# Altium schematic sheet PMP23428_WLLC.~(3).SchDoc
size 431 x 279 mm; Date: Not shown in title block; ApprovedBy: Not shown in title block; CheckedBy: Not shown in title block; Author: Not shown in title block; CompanyName: Not shown in title block; Engineer: Not shown in title block; Organization: Not shown in title block; Address1: Not shown in title block; Address2: Not shown in title block; Address3: Not shown in title block; Address4: Not shown in title block; DocumentNumber: 1; Revision: Use project parameter SCH_Rev; SheetNumber: 3; SheetTotal: 4; PageSetup: Record=PageOptions¦CenterHorizontal=True¦CenterVertical=True¦PrintScale=1.00¦XCorrection=1.00¦YCorrection=1.00¦PrintKind=0¦BorderSize=5000000¦LeftOffset=0¦BottomOffset=0¦Orientation=2¦PaperLength=1000¦PaperWidth=1000¦Scale=100¦PaperSource=15¦PrintQuality=600¦MediaType=1¦DitherType=10¦PaperKind=Letter¦PrintScaleMode=1
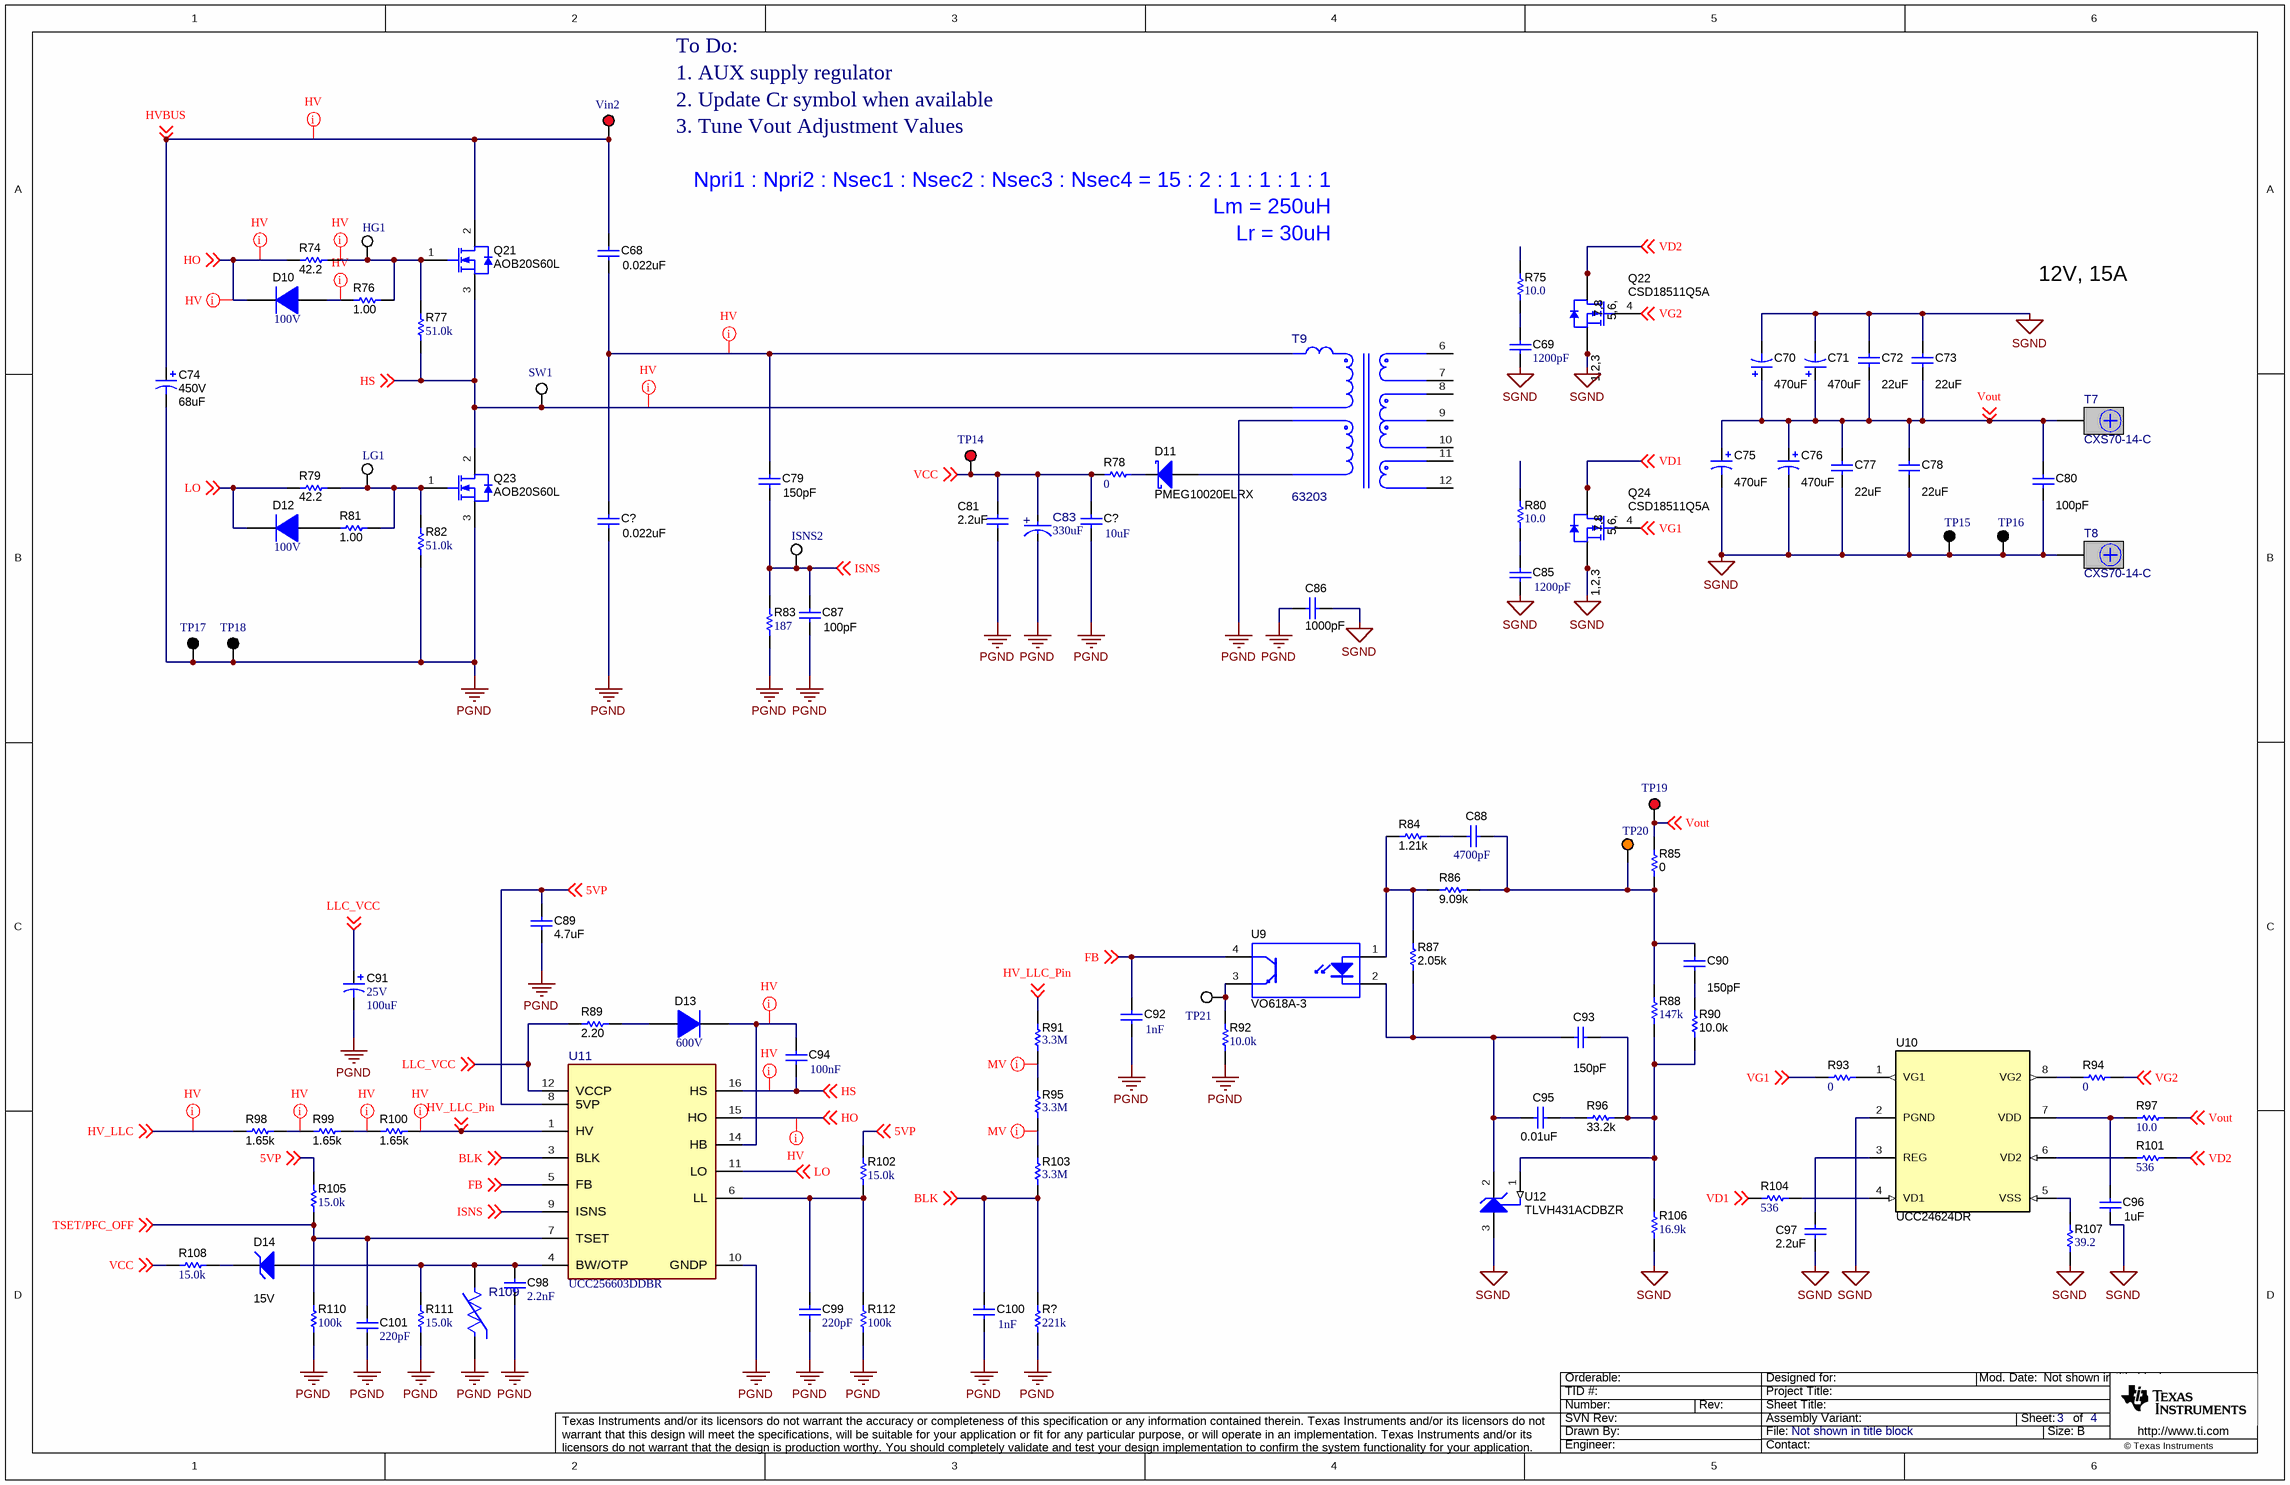
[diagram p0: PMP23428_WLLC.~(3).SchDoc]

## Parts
(Parts that share a designator on the sheet are numbered #1, #2 ... from top to bottom, then left to right.)
C68  ValueDisplayed: 0.022uF  [B32652_1800x700x1250]  (hidden comment: B32652A7153J000)
C69  ValueDisplayed: 1200pF  [0805L]  (hidden comment: GRM2165C2A122JA01D)
C70  ValueDisplayed: 470uF  [HW_1000x1600]  (hidden comment: UHW1V471MPD)
C71  ValueDisplayed: 470uF  [HW_1000x1600]  (hidden comment: UHW1V471MPD)
C72  ValueDisplayed: 22uF  [1206_190L]  (hidden comment: C3216X5R1E226M160AB)
C73  ValueDisplayed: 22uF  [1206_190L]  (hidden comment: C3216X5R1E226M160AB)
C74  VDC_V: 450V  ValueDisplayed: 68uF  [KXG_1800x3150]  (hidden comment: EKXG451ELL680MMN3S)
C75  ValueDisplayed: 470uF  [HW_1000x1600]  (hidden comment: UHW1V471MPD)
C76  ValueDisplayed: 470uF  [HW_1000x1600]  (hidden comment: UHW1V471MPD)
C77  ValueDisplayed: 22uF  [1206_190L]  (hidden comment: C3216X5R1E226M160AB)
C78  ValueDisplayed: 22uF  [1206_190L]  (hidden comment: C3216X5R1E226M160AB)
C79  ValueDisplayed: 150pF  [1206L]  (hidden comment: GRM31A5C2J151JW01D)
C80  ValueDisplayed: 100pF  [0603L]  (hidden comment: 06035A101FAT2A)
C81  ValueDisplayed: 2.2uF  [0805L]  (hidden comment: C2012X7R1V225K085AC)
C83  ValueDisplayed: 330uF  [FP-35ZL330MEFC10X16_RADIAL-MFG]  (hidden comment: 35ZL330MEFC10X16)
C85  ValueDisplayed: 1200pF  [0805L]  (hidden comment: GRM2165C2A122JA01D)
C86  ValueDisplayed: 1000pF  [CD45_700x600x1100]  (hidden comment: CD45-E2GA102M-NKA)
C87  ValueDisplayed: 100pF  [1206L]  (hidden comment: 12061A101JAT2A)
C88  ValueDisplayed: 4700pF  [0603L]  (hidden comment: C0603C472J1GAC7867)
C89  ValueDisplayed: 4.7uF  [1206L]  (hidden comment: C3216X7R1E475K085AB)
C90  ValueDisplayed: 150pF  [0402L]  (hidden comment: 885012005062)
C91  VDC_V: 25V  ValueDisplayed: 100uF  [SM_RADIAL_E]  (hidden comment: EEE-FK1E101P)
C92  Cap_F: 1nF  [1206L]  (hidden comment: 12061A102JAT2A)
C93  ValueDisplayed: 150pF  [0402L]  (hidden comment: 885012005062)
C94  Cap_F: 100nF  [1206_180L]  (hidden comment: GRM31C5C1E104JA01L)
C95  ValueDisplayed: 0.01uF  [0603L]  (hidden comment: 06031C103JAT2A)
C96  ValueDisplayed: 1uF  [0603L]  (hidden comment: GRM188R71C105KE15D)
C97  ValueDisplayed: 2.2uF  [0805L]  (hidden comment: C2012X7R1V225K085AC)
C98  Cap_F: 2.2nF  [0603]  (hidden comment: C0603X222K5RACTU)
C99  Cap_F: 220pF  [0603]  (hidden comment: C0603X221K5RACTU)
C100  Cap_F: 1nF  [0402L]  (hidden comment: 04025C102JAT2A)
C101  Cap_F: 220pF  [0603]  (hidden comment: C0603X221K5RACTU)
C?#1  ValueDisplayed: 0.022uF  [B32652_1800x700x1250]  (hidden comment: B32652A7153J000)
C?#2  ValueDisplayed: 10uF  [1210_270]  (hidden comment: GRM32ER6YA106KA12L)
D10  Vr_V: 100V  [SOD-123]  (hidden comment: 1N4148W-7-F)
D11  PMEG10020ELRX  [SOD-123W]
D12  Vr_V: 100V  [SOD-123]  (hidden comment: 1N4148W-7-F)
D13  Vr_V: 600V  [SMAF]  (hidden comment: ES1JAF)
D14  value 15V  [SOD-123]  (hidden comment: DDZ15-7)
HG1  5012  [Keystone5012]  (value not drawn)
ISNS2  5012  [Keystone5012]  (value not drawn)
LG1  5012  [Keystone5012]  (value not drawn)
Q21  AOB20S60L  [DDPAK]
Q22  CSD18511Q5A  [DQJ0008A]
Q23  AOB20S60L  [DDPAK]
Q24  CSD18511Q5A  [DQJ0008A]
R74  ValueDisplayed: 42.2  [0603]  (hidden comment: RC0603FR-0742R2L)
R75  ValueDisplayed: 10.0  [1206L]  (hidden comment: RC1206FR-0710RL)
R76  ValueDisplayed: 1.00  [0603L]  (hidden comment: RC0603FR-071RL)
R77  ValueDisplayed: 51.0k  [0603L]  (hidden comment: RC0603FR-0751KL)
R78  ValueDisplayed: 0  [1206L]  (hidden comment: ERJ-8GEY0R00V)
R79  ValueDisplayed: 42.2  [0603L]  (hidden comment: RC0603FR-0742R2L)
R80  ValueDisplayed: 10.0  [1206L]  (hidden comment: RC1206FR-0710RL)
R81  ValueDisplayed: 1.00  [0603L]  (hidden comment: RC0603FR-071RL)
R82  ValueDisplayed: 51.0k  [0603L]  (hidden comment: RC0603FR-0751KL)
R83  ValueDisplayed: 187  [1206]  (hidden comment: RC1206FR-07187RL)
R84  ValueDisplayed: 1.21k  [0603L]  (hidden comment: RC0603FR-071K21L)
R85  ValueDisplayed: 0  [0402L]  (hidden comment: RC0402JR-070RL)
R86  ValueDisplayed: 9.09k  [0603L]  (hidden comment: RC0603FR-079K09L)
R87  ValueDisplayed: 2.05k  [0603L]  (hidden comment: RC0603FR-072K05L)
R88  ValueDisplayed: 147k  [0603L]  (hidden comment: RC0603FR-07147KL)
R89  ValueDisplayed: 2.20  [0603L]  (hidden comment: ERJ-3RQF2R2V)
R90  ValueDisplayed: 10.0k  [0603L]  (hidden comment: ERJ-3EKF1002V)
R91  Res_ohm: 3.3M  [FP-KTR18EZPF3304_1206-MFG]  (hidden comment: KTR18EZPF3304)
R92  ValueDisplayed: 10.0k  [0402L]  (hidden comment: ERJ-2RKF1002X)
R93  ValueDisplayed: 0  [0603L]  (hidden comment: RC0603JR-070RL)
R94  ValueDisplayed: 0  [0603L]  (hidden comment: RC0603JR-070RL)
R95  Res_ohm: 3.3M  [FP-KTR18EZPF3304_1206-MFG]  (hidden comment: KTR18EZPF3304)
R96  ValueDisplayed: 33.2k  [0603L]  (hidden comment: RC0603FR-0733K2L)
R97  ValueDisplayed: 10.0  [0603L]  (hidden comment: RC0603FR-0710RL)
R98  ValueDisplayed: 1.65k  [1206L]  (hidden comment: CRCW12061K65FKEA)
R99  ValueDisplayed: 1.65k  [1206L]  (hidden comment: CRCW12061K65FKEA)
R100  ValueDisplayed: 1.65k  [1206L]  (hidden comment: CRCW12061K65FKEA)
R101  ValueDisplayed: 536  [0603L]  (hidden comment: RT0603BRD07536RL)
R102  ValueDisplayed: 15.0k  [0603]  (hidden comment: RT0603BRD0715KL)
R103  Res_ohm: 3.3M  [FP-KTR18EZPF3304_1206-MFG]  (hidden comment: KTR18EZPF3304)
R104  ValueDisplayed: 536  [0603L]  (hidden comment: RT0603BRD07536RL)
R105  ValueDisplayed: 15.0k  [0603]  (hidden comment: RT0603BRD0715KL)
R106  ValueDisplayed: 16.9k  [0603L]  (hidden comment: RC0603FR-0716K9L)
R107  ValueDisplayed: 39.2  [0603L]  (hidden comment: RC0603FR-0739R2L)
R108  ValueDisplayed: 15.0k  [0603]  (hidden comment: RG1608P-153-B-T5)
R109  B57371V2474J060  [FP-B57371V2474J060_0603-MFG]  (value not drawn)
R110  ValueDisplayed: 100k  [0603]  (hidden comment: RT0603BRD07100KL)
R111  ValueDisplayed: 15.0k  [0603]  (hidden comment: RG1608P-153-B-T5)
R112  ValueDisplayed: 100k  [0603]  (hidden comment: RT0603BRD07100KL)
R?  ValueDisplayed: 221k  [0603]  (hidden comment: RC0603FR-07221KL)
SW1  5012  [Keystone5012]  (value not drawn)
T7  CXS70-14-C  [Panduit_CXS70-14-C]
T8  CXS70-14-C  [Panduit_CXS70-14-C]
T9  63203  [FP-63203_W80MM0_H64MM0-MFG]
TP14  5010  [Keystone5010]  (value not drawn)
TP15  5011  [Keystone5011]  (value not drawn)
TP16  5011  [Keystone5011]  (value not drawn)
TP17  5011  [Keystone5011]  (value not drawn)
TP18  5011  [Keystone5011]  (value not drawn)
TP19  5010  [Keystone5010]  (value not drawn)
TP20  5013  [Keystone5013]  (value not drawn)
TP21  5012  [Keystone5012]  (value not drawn)
U9  VO618A-3  [DIP-4]
U10  UCC24624DR  [D0008A_N]
U11  UCC256603DDBR  [DDB0014A-MFG]
U12  TLVH431ACDBZR  [DBZ0003A_N]
Vin2  5010  [Keystone5010]  (value not drawn)

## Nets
PGND: C74.2(-) C81.2 C83.1(CATHODE) C86.2 C87.2 C89.2 C91.2(-) C92.2 C98.2 C99.2 C100.2 C101.2 C?#1.2 C?#2.2 Q23.3(S) R82.1 R83.1 R92.1 R109.1 R110.1 R111.1 R112.1 R?.1 TP17.1 TP18.1 U11.10(GNDP)
SGND: C69.2 C70.2(-) C71.2(-) C72.1 C73.1 C75.2(-) C76.2(-) C77.2 C78.2 C80.2 C85.2 C86.1 C96.2 C97.2 Q22.1(S) Q22.2(S) Q22.3(S) Q24.1(S) Q24.2(S) Q24.3(S) R106.1 R107.2 T8.1 TP15.1 TP16.1 U10.2(PGND) U12.3(ANODE)
5VP: C89.1 R102.2 R105.2 U11.8(5VP) ; off-sheet 5VP
BLK: C100.1 R103.1 R?.2 U11.3(BLK) ; off-sheet BLK
FB: C92.1 U9.4(C) U11.5(FB) ; off-sheet FB
HO: D10.1(K) R74.1 U11.15(HO) ; off-sheet HO
HS: C94.2 Q21.3(S) Q23.2(D) R77.1 SW1.1 U11.16(HS) ; off-sheet HS
HV_LLC: R98.1 ; off-sheet HV_LLC
HV_LLC_Pin: R91.2 R100.2 U11.1(HV) ; off-sheet HV_LLC_Pin
HVBUS: C68.1 C74.1(+) Q21.2(D) Vin2.1 ; off-sheet HVBUS
ISNS: C79.2 C87.1 ISNS2.1 R83.2 U11.9(ISNS) ; off-sheet ISNS
LLC_VCC: C91.1(+) R89.1 U11.12(VCCP) ; off-sheet LLC_VCC
LO: D12.1(K) R79.1 U11.11(LO) ; off-sheet LO
TSET/PFC_OFF: C101.1 R105.1 R110.2 U11.7(TSET) ; off-sheet TSET/PFC_OFF
VCC: C81.1 C83.2(ANODE) C?#2.1 R78.1 R108.2 TP14.1 ; off-sheet VCC
VD1: Q24.5(D) Q24.6(D) Q24.7(D) Q24.8(D) Q24.9(D) R104.2 ; off-sheet VD1
VD2: Q22.5(D) Q22.6(D) Q22.7(D) Q22.8(D) Q22.9(D) R101.1 ; off-sheet VD2
VG1: Q24.4(G) R93.1 ; off-sheet VG1
VG2: Q22.4(G) R94.2 ; off-sheet VG2
Vout: C70.1(+) C71.1(+) C72.2 C73.2 C75.1(+) C76.1(+) C77.1 C78.1 C80.1 R85.2 R97.2 T7.1 TP19.1 ; off-sheet Vout
NetC68_2: C68.2 C79.1 C?#1.1
NetC69_1: C69.1 R75.1
NetC85_1: C85.1 R80.1
NetC88_1: C88.1 C90.1 R85.1 R86.2 R88.2 TP20.1
NetC88_2: C88.2 R84.2
NetC90_2: C90.2 R90.2
NetC93_1: C93.1 R88.1 R90.1 R96.1 R106.2 U12.1(REF)
NetC93_2: C93.2 C95.2 R87.1 U9.2(K) U12.2(CATHODE)
NetC94_1: C94.1 D13.1(K) U11.14(HB)
NetC95_1: C95.1 R96.2
NetC96_1: C96.1 R97.1 U10.7(VDD)
NetC97_1: C97.1 U10.3(REG)
NetC98_1: C98.1 D14.2(A) R109.2 R111.2 U11.4(BW/OTP)
NetC99_1: C99.1 R102.1 R112.2 U11.6(LL)
NetD10_2: D10.2(A) R76.1
NetD11_1: D11.1(K) R78.2
NetD12_2: D12.2(A) R81.1
NetD13_2: D13.2(A) R89.2
NetD14_1: D14.1(K) R108.1
NetHG1_1: HG1.1 Q21.1(G) R74.2 R76.2 R77.2
NetLG1_1: LG1.1 Q23.1(G) R79.2 R81.2 R82.2
NetR84_1: R84.1 R86.1 R87.2 U9.1(A)
NetR91_1: R91.1 R95.2
NetR92_2: R92.2 TP21.1 U9.3(E)
NetR93_2: R93.2 U10.1(VG1)
NetR94_1: R94.1 U10.8(VG2)
NetR95_1: R95.1 R103.2
NetR98_2: R98.2 R99.1
NetR99_2: R99.2 R100.1
NetR101_2: R101.2 U10.6(VD2)
NetR104_1: R104.1 U10.4(VD1)
NetR107_1: R107.1 U10.5(VSS)

Not connected (* = marked no-connect by the designer): D11 2(A); R75 2; R80 2; T9 6 7 8 9 10 11 12

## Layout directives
net class HV: HO, HS, HV_LLC, HV_LLC_Pin, HVBUS, NetC68_2, NetC94_1, NetD10_2, NetHG1_1, NetR98_2, NetR99_2
net class MV: NetR91_1, NetR95_1

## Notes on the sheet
- To Do:
- 1. AUX supply regulator
- 2. Update Cr symbol when available
- 3. Tune Vout Adjustment Values
- Lm = 250uH
- Lr = 30uH
- Npri1 : Npri2 : Nsec1 : Nsec2 : Nsec3 : Nsec4 = 15 : 2 : 1 : 1 : 1 : 1
- 12V, 15A

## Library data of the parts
C68 C?#1 = CMP-0012346-3: Manufacturer: TDK; TaMin_C: -55°C; Polarized: N; SizeAreaWB_mm2: 180; Value1: Unknown; Value: 0.015uF; TaMax_C: 100°C; Tolerance_%: 5%; SizeZ_mm: 12.5; SizeX_mm: 18; SizeY_mm: 7; Cap_Case: 18x7x12.5; Value2: 1250V; SizeArea_mm2: 126; CompType: Capacitor; AEC Qualified: Y; Cap_F: 15nF; VDC_V: 1.25kV; AEC Grade: 3; AEC Category: Q200
C69 C85 = CMP-0008098-2: CAP, CERM, 1200 pF, 100 V, +/- 5%, C0G/NP0, 0805; Manufacturer: MuRata; TaMin_C: -55°C; Polarized: N; SizeAreaWB_mm2: 6.75; Value1: Unknown; U/M: EA; Value: 1200pF; TaMax_C: 125°C; SizeZ_mm: 1.45; SizeX_mm: 2; SizeY_mm: 1.25; Cap_Case: 0805; Value2: 100V; SizeArea_mm2: 2.5; Cap_F: 1.2nF; AEC Category: Q200
C70 C71 C75 C76 = CMP-0010541-2: CAP, AL, 470 uF, 35 V, +/- 20%, 0.03 ohm, TH; Manufacturer: Nichicon; TaMin_C: -40°C; ESR_ohm: 0.03; Polarized: Y; SizeAreaWB_mm2: 144; U/M: EA; Value: 470uF; TaMax_C: 105°C; SizeZ_mm: 17.5; SizeX_mm: 10; Cap_Case: 10x16mm; Value2: 35V; SizeArea_mm2: 100; CompType: Capacitor; AEC Qualified: N; Cap_F: 470µF; IRMS_A: 2A; AEC Category: Q200
C72 C73 C77 C78 = CMP-0008654-2: CAP, CERM, 22 uF, 25 V, +/- 20%, X5R, 1206_190; Manufacturer: TDK; TaMin_C: -55°C; Polarized: N; SizeAreaWB_mm2: 10.92; Value1: Unknown; U/M: EA; Value: 22uF; TaMax_C: 85°C; SizeZ_mm: 1.9; SizeX_mm: 3.2; SizeY_mm: 1.6; Cap_Case: 1206; Value2: 25V; SizeArea_mm2: 5.12; CompType: Capacitor; Cap_F: 22µF; AEC Category: Q200
C74 = CMP-0010043-2: CAP, AL, 68 uF, 450 V, +/- 20%, TH; Manufacturer: Chemi-Con; TaMin_C: -25°C; Polarized: Y; SizeAreaWB_mm2: 400; Value1: Unknown; U/M: EA; Value: 68uF; TaMax_C: 105°C; SizeZ_mm: 33; SizeX_mm: 18; Cap_Case: 18x31.5mm; SizeArea_mm2: 324; CompType: Capacitor; Cap_F: 68µF; IRMS_A: 6.3dA; AEC Category: Q200
C79 = CMP-0008885-2: CAP, CERM, 150 pF, 630 V, +/- 5%, C0G/NP0, 1206; Manufacturer: MuRata; TaMin_C: -55°C; Polarized: N; SizeAreaWB_mm2: 10.92; Value1: Unknown; U/M: EA; Value: 150pF; TaMax_C: 125°C; SizeZ_mm: 1.35; SizeX_mm: 3.2; SizeY_mm: 1.6; Cap_Case: 1206; Value2: 630V; SizeArea_mm2: 5.12; CompType: Capacitor; AEC Category: Q200
C80 = CMP-0006762-4: CAP, CERM, 100 pF, 50 V, +/- 1%, C0G/NP0, 0603; Manufacturer: AVX; TaMin_C: -55°C; Polarized: N; SizeAreaWB_mm2: 4.68; Value1: Unknown; U/M: EA; TaMax_C: 125°C; SizeZ_mm: 1; SizeX_mm: 1.6; SizeY_mm: 0.8; Cap_Case: 0603; Value2: 50V; SizeArea_mm2: 1.28; CompType: Capacitor; Value: 100pF; AEC Category: Q200
C81 C97 = CMP-0007883-2: CAP, CERM, 2.2 uF, 35 V, +/- 10%, X7R, 0805; Manufacturer: TDK; TaMin_C: -55°C; Polarized: N; SizeAreaWB_mm2: 6.75; Value1: Unknown; U/M: EA; Value: 2.2uF; TaMax_C: 125°C; SizeZ_mm: 1.45; SizeX_mm: 2; SizeY_mm: 1.25; Cap_Case: 0805; Value2: 35V; SizeArea_mm2: 2.5; CompType: Capacitor; Cap_F: 2.2µF; AEC Category: Q200
C83 = CMP-0098283-1: Cap Aluminum Lytic 330uF 35V 20% (10 X 16mm) Radial 5mm 1430mA 4000h 105C Bulk; Manufacturer: Rubycon; AEC Qualified: No; Cap_F: 330µF; IRMS_A: 1.43A; SizeZ_mm: 17.5mm; Dissipation Factor: 12%; Leakage Current: 115.5uA; Life: 4000Hours; Value: 330µF
C86 = CMP-0009595-2: CAP, CERM, 1000 pF,  V, +/- 20%, E, D7xT6mm; Manufacturer: TDK; TaMin_C: -25°C; Polarized: N; SizeAreaWB_mm2: 101.2; Value1: Unknown; U/M: EA; Value: 1000pF; TaMax_C: 125°C; SizeZ_mm: 11; SizeX_mm: 10.65; SizeY_mm: 6; Cap_Case: 7x6x11mm; SizeArea_mm2: 63.9; Cap_F: 1nF; AEC Category: Q200
C87 = CMP-0008462-2: CAP, CERM, 100 pF, 100 V, +/- 5%, C0G/NP0, 1206; Manufacturer: AVX; TaMin_C: -55°C; ESR_ohm: 7.01d; Polarized: N; SizeAreaWB_mm2: 10.92; Value1: 0.701 ohm; U/M: EA; Value: 100pF; TaMax_C: 125°C; SizeZ_mm: 1.35; SizeX_mm: 3.2; SizeY_mm: 1.6; Cap_Case: 1206; Value2: 100V; SizeArea_mm2: 5.12; CompType: Capacitor; AEC Category: Q200
C88 = CMP-0006941-4: CAP, CERM, 4700 pF, 100 V, +/- 5%, C0G/NP0, 0603; Manufacturer: Kemet; TaMin_C: -55°C; Polarized: N; SizeAreaWB_mm2: 4.68; Value1: Unknown; U/M: EA; Value: 4700pF; TaMax_C: 125°C; SizeZ_mm: 1; SizeX_mm: 1.6; SizeY_mm: 0.8; Cap_Case: 0603; Value2: 100V; SizeArea_mm2: 1.28; Cap_F: 4.7nF; AEC Category: Q200
C89 = CMP-0008693-2: CAP, CERM, 4.7 uF, 25 V, +/- 10%, X7R, 1206; Manufacturer: TDK; TaMin_C: -55°C; Polarized: N; SizeAreaWB_mm2: 10.92; Value1: Unknown; U/M: EA; Value: 4.7uF; TaMax_C: 125°C; SizeZ_mm: 1.35; SizeX_mm: 3.2; SizeY_mm: 1.6; Cap_Case: 1206; Value2: 25V; SizeArea_mm2: 5.12; CompType: Capacitor; Cap_F: 4.7µF; AEC Category: Q200
C90 C93 = CMP-0064913-2: CAP, CERM, 150 pF, 50 V,+/- 5%, C0G/NP0, 0402; Manufacturer: Wurth Elektronik; TaMin_C: -55°C; Polarized: N; SizeAreaWB_mm2: 3; Value1: Unknown; U/M: EA; Value: 150pF; TaMax_C: 125°C; SizeZ_mm: 0.6; SizeX_mm: 1; SizeY_mm: 0.5; Cap_Case: 0402; Value2: 50V; CompType: Capacitor; AEC Category: Q200
C91 = CMP-0010710-1: CAP, AL, 100 uF, 25 V, +/- 20%, 0.26 ohm, AEC-Q200 Grade 2, SMD; Manufacturer: Panasonic; TaMin_C: -55°C; ESR_ohm: 2.6d; Polarized: Y; SizeAreaWB_mm2: 118.45; U/M: EA; Value: 100uF; TaMax_C: 105°C; SizeZ_mm: 6.2; SizeX_mm: 9.5; SizeY_mm: 8.3; Cap_Case: E; SizeArea_mm2: 78.85; CompType: Capacitor; Cap_F: 100µF; IRMS_A: 3dA; AEC Grade: 2; AEC Category: Q200
C92 = CMP-0008465-2: CAP, CERM, 1000 pF, 100 V, +/- 5%, C0G/NP0, 1206; Manufacturer: AVX; TaMin_C: -55°C; ESR_ohm: 2.38d; Polarized: N; SizeAreaWB_mm2: 10.92; Value1: 0.238 ohm; U/M: EA; Value: 1000pF; TaMax_C: 125°C; SizeZ_mm: 1.35; SizeX_mm: 3.2; SizeY_mm: 1.6; Cap_Case: 1206; Value2: 100V; SizeArea_mm2: 5.12; AEC Category: Q200
C94 = CMP-0064950-2: CAP, CERM, 0.1 uF, 25 V,+/- 5%, C0G/NP0, 1206; Manufacturer: MuRata; TaMin_C: -55°C; Polarized: N; SizeAreaWB_mm2: 10.92; Value1: Unknown; U/M: EA; Value: 0.1uF; TaMax_C: 125°C; SizeZ_mm: 1.8; SizeX_mm: 3.2; SizeY_mm: 1.6; Cap_Case: 1206; Value2: 25V; SizeArea_mm2: 5.12; AEC Category: Q200
C95 = CMP-0006726-4: CAP, CERM, 0.01 uF, 100 V, +/- 5%, X7R, 0603; Manufacturer: AVX; TaMin_C: -55°C; ESR_ohm: 0.098; Polarized: N; SizeAreaWB_mm2: 4.68; Value1: 0.098 ohm; U/M: EA; Value: 0.01uF; TaMax_C: 125°C; SizeZ_mm: 1; SizeX_mm: 1.6; SizeY_mm: 0.8; Cap_Case: 0603; Value2: 100V; SizeArea_mm2: 1.28; Cap_F: 10nF; AEC Category: Q200
C96 = CMP-0007380-4: CAP, CERM, 1 uF, 16 V, +/- 10%, X7R, 0603; Manufacturer: MuRata; TaMin_C: -55°C; Polarized: N; SizeAreaWB_mm2: 4.68; Value1: Unknown; U/M: EA; Value: 1uF; TaMax_C: 125°C; SizeZ_mm: 1; SizeX_mm: 1.6; SizeY_mm: 0.8; Cap_Case: 0603; Value2: 16V; SizeArea_mm2: 1.28; CompType: Capacitor; Cap_F: 1µF; AEC Category: Q200
C98 = CMP-0006983-4: CAP, CERM, 2200 pF, 50 V, +/- 10%, X7R, 0603; Manufacturer: Kemet; TaMin_C: -55°C; Polarized: N; SizeAreaWB_mm2: 4.68; Value1: Unknown; U/M: EA; Value: 2200pF; TaMax_C: 125°C; SizeZ_mm: 1; SizeX_mm: 1.6; SizeY_mm: 0.8; Value2: 50V; SizeArea_mm2: 1.28; AEC Category: Q200
C99 C101 = CMP-0006982-4: CAP, CERM, 220 pF, 50 V, +/- 10%, X7R, 0603; Manufacturer: Kemet; TaMin_C: -55°C; Polarized: N; SizeAreaWB_mm2: 4.68; Value1: Unknown; U/M: EA; Value: 220pF; TaMax_C: 125°C; SizeZ_mm: 1; SizeX_mm: 1.6; SizeY_mm: 0.8; Value2: 50V; SizeArea_mm2: 1.28; AEC Category: Q200
C100 = CMP-0861060-1: CAP, CERM, 1000 pF, 50 V,+/- 5%, X7R, 0402; Manufacturer: AVX; Value2: 50V; SizeY_mm: 0.5; AEC Category: Q200; Polarized: N; Green_Lifecycle: Active; SizeAreaWB_mm2: 3; ValueDisplayed: 1000pF; Cap_Case: 0402; Value: 1000pF; TaMin_C: -55°C; U/M: EA; Green_REACh: Passed; SizeZ_mm: 0.6; SizeX_mm: 1; TaMax_C: 125°C
C?#2 = CMP-0009215-2: CAP, CERM, 10 uF, 35 V, +/- 10%, X5R, 1210; Manufacturer: MuRata; TaMin_C: -55°C; Polarized: N; SizeAreaWB_mm2: 14.7; Value1: Unknown; U/M: EA; Value: 10uF; TaMax_C: 85°C; SizeZ_mm: 2.7; SizeX_mm: 3.2; SizeY_mm: 2.5; Cap_Case: 1210; Value2: 35V; SizeArea_mm2: 8; Cap_F: 10µF; AEC Category: Q200
D10 D12 = CMP-0029001-2: Diode, Ultrafast, 100 V, 0.15 A, SOD-123; Manufacturer: Diodes Inc.; Io_A: 150mA; Green_Lifecycle: Active; SizeAreaWB_mm2: 13.095; Green_REACh: Passed; Value1: 0.15A; TJmax_C: 150°C; Value: 100V; SizeZ_mm: 1.35; SizeX_mm: 3.85; SizeY_mm: 1.7; Vf_V: 1.25V; SizeArea_mm2: 6.545; AEC Category: Q101
D11 = CMP-0028977-2: Diode, Schottky, 100 V, 2 A, AEC-Q101, SOD-123W; Manufacturer: Nexperia; Io_A: 2A; SizeAreaWB_mm2: 12.15; Vr_V: 100V; TJmax_C: 175°C; Value: 100V; SizeZ_mm: 1; SizeX_mm: 3.5; SizeY_mm: 1.7; Vf_V: 830mV; Value2: 0.83V; SizeArea_mm2: 5.95; AEC Qualified: Y; AEC Category: Q101
D13 = CMP-0029162-2: Diode, Ultrafast, 600 V, 1 A, AEC-Q101, SMAF; Manufacturer: Fairchild Semiconductor; Io_A: 1A; Green_Lifecycle: Not Set; SizeAreaWB_mm2: 19.95; Green_REACh: Incomplete; TJmax_C: 150°C; Value: 600V; SizeZ_mm: 1; SizeX_mm: 4.7; SizeY_mm: 2.5; Vf_V: 1.7V; SizeArea_mm2: 11.75; AEC Qualified: Y; AEC Category: Q101
D14 = CMP-0085135-1: Diode, Zener, 15 V, 500 mW, SOD-123; Manufacturer: Diodes Inc.; SizeAreaWB_mm2: 13.095; SizeArea_mm2: 6.545; SizeY_mm: 1.7; AEC Qualified: N; SizeZ_mm: 1.35; Value1: 0.5W; SizeX_mm: 3.85; Power_W: 500mW; RJA_CperW: 425; AEC Category: Q101
HG1 ISNS2 LG1 SW1 TP21 = CMP-0055149-2: Test Point, Multipurpose, White, TH; Manufacturer: Keystone Electronics; CNHeader: FALSE; Green_Lifecycle: Active; Green_REACh: Passed; ContactFinish: Silver; CT: TRUE
Q21 Q23 = CMP-0001135-4: MOSFET, N-CH, 600 V, 20 A, DDPAK; Alternate Manufacturer: None; Manufacturer: AOS; SizeZ_mm: 4.445; ChType: N; Value2: 19.8 nC; VdsMax_V: 600V; SizeX_mm: 15.245; SizeAreaWB_mm2: 209.6992; SizeY_mm: 10.16; Vgs_V: 30V; QgTyp_nC: 19.8; Value: 600V; SizeArea_mm2: 154.8892; AEC Category: Q101; IdsMax_A: 20A; ChMode: Enhancement
Q22 Q24 = CMP-0000711-1: MOSFET, N-CH, 40 V, 100 A, DQJ0008A (VSONP-8); Alternate Manufacturer: None; Manufacturer: Texas Instruments; SizeZ_mm: 1.1; ChType: N; Value2: 63 nC; Value1: 0.003; VdsMax_V: 40V; SizeX_mm: 6; SizeY_mm: 4.9; Vgs_V: 20V; Value: 40V; Rdson45_ohm: 3.5m; SizeArea_mm2: 29.4; AEC Category: Q101; IdsMax_A: 100A; SizeAreaWB_mm2: 55.2; U/M: EA; QgTyp_nC: 63
R74 R79 = CMP-0023107-5: RES, 42.2, 1%, 0.1 W, 0603; Manufacturer: Yageo; Power_W: 100mW; TempCo: 100 ppm/C; Value_Code: 42R2; Value: 42.2; EIA_Code: E96; SizeX_mm: 1.6; SizeY_mm: 0.8; SizeZ_mm: 1; Value2: 0.1W; SizeArea_mm2: 1.28; CompType: Resistor; AEC Qualified: N; VDC_V: 75V; AEC Category: Q200; SizeAreaWB_mm2: 4.68
R75 R80 = CMP-0017851-2: RES, 10.0, 1%, 0.25 W, 1206; Manufacturer: Yageo America; Power_W: 250mW; TempCo: 200 ppm/C; Value_Code: 10R0; U/M: EA; Value: 10.0; EIA_Code: E96; Res_ohm: 10; SizeX_mm: 3.2; SizeY_mm: 1.6; SizeZ_mm: 1.35; Value2: 0.25W; SizeArea_mm2: 5.12; VDC_V: 200V; AEC Category: Q200
R76 R81 = CMP-0022900-4: RES, 1.00, 1%, 0.1 W, 0603; Manufacturer: Yageo; Power_W: 100mW; TempCo: 200 ppm/C; Value_Code: 1R00; Value: 1.00; EIA_Code: E96; Res_ohm: 1; SizeX_mm: 1.6; SizeY_mm: 0.8; Value2: 0.1W; SizeArea_mm2: 1.28; CompType: Resistor; AEC Qualified: N; VDC_V: 75V; AEC Category: Q200; SizeAreaWB_mm2: 4.68
R77 R82 = CMP-0023167-5: RES, 51.0 k, 1%, 0.1 W, 0603; Manufacturer: Yageo; Power_W: 100mW; TempCo: 100 ppm/C; Value_Code: 51k0; Value: 51.0k; Res_ohm: 51k; SizeX_mm: 1.6; SizeY_mm: 0.8; SizeZ_mm: 1; Value2: 0.1W; SizeArea_mm2: 1.28; AEC Qualified: N; VDC_V: 75V; AEC Category: Q200; SizeAreaWB_mm2: 4.68
R78 = CMP-0018748-3: RES, 0, 5%, 0.25 W, AEC-Q200 Grade 0, 1206; Manufacturer: Panasonic; Power_W: 250mW; TempCo: 600 ppm/C; Value_Code: 0000; Value: 0; EIA_Code: E24; SizeX_mm: 3.2; SizeY_mm: 1.6; SizeZ_mm: 1.35; Value2: 0.25W; SizeArea_mm2: 5.12; AEC Qualified: Y; VDC_V: 200V; AEC Category: Q200; SizeAreaWB_mm2: 10.92
R83 = CMP-0017949-2: RES, 187, 1%, 0.25 W, 1206; Manufacturer: Yageo America; Power_W: 250mW; TempCo: 100 ppm/C; Value_Code: 187R; U/M: EA; Value: 187; EIA_Code: E96; SizeX_mm: 3.2; SizeY_mm: 1.6; SizeZ_mm: 1.35; Value2: 0.25W; SizeArea_mm2: 5.12; VDC_V: 200V; AEC Category: Q200
R84 = CMP-0022871-5: RES, 1.21 k, 1%, 0.1 W, 0603; Manufacturer: Yageo; Power_W: 100mW; TempCo: 100 ppm/C; Value_Code: 1k21; Value: 1.21k; EIA_Code: E96; SizeX_mm: 1.6; SizeY_mm: 0.8; SizeZ_mm: 1; Value2: 0.1W; SizeArea_mm2: 1.28; AEC Qualified: N; VDC_V: 75V; AEC Category: Q200; SizeAreaWB_mm2: 4.68
R85 = CMP-0027004-2: RES, 0, 5%, 0.063 W, 0402; Manufacturer: Yageo America; Power_W: 63mW; TempCo: 200 ppm/C; Value_Code: 0000; U/M: EA; Value: 0; EIA_Code: E24; SizeX_mm: 1; SizeY_mm: 0.5; SizeZ_mm: 0.6; Value2: 0.063W; CompType: Resistor; VDC_V: 50V; AEC Category: Q200
R86 = CMP-0023332-5: RES, 9.09 k, 1%, 0.1 W, 0603; Manufacturer: Yageo; Power_W: 100mW; TempCo: 100 ppm/C; Value_Code: 9k09; Value: 9.09k; EIA_Code: E96; SizeX_mm: 1.6; SizeY_mm: 0.8; SizeZ_mm: 1; Value2: 0.1W; SizeArea_mm2: 1.28; AEC Qualified: N; VDC_V: 75V; AEC Category: Q200; SizeAreaWB_mm2: 4.68
R87 = CMP-0022981-5: RES, 2.05 k, 1%, 0.1 W, 0603; Manufacturer: Yageo; Power_W: 100mW; TempCo: 100 ppm/C; Value_Code: 2k05; Value: 2.05k; EIA_Code: E96; SizeX_mm: 1.6; SizeY_mm: 0.8; SizeZ_mm: 1; Value2: 0.1W; SizeArea_mm2: 1.28; AEC Qualified: N; VDC_V: 75V; AEC Category: Q200; SizeAreaWB_mm2: 4.68
R88 = CMP-0022800-4: RES, 147 k, 1%, 0.1 W, 0603; Manufacturer: Yageo; Power_W: 100mW; TempCo: 100 ppm/C; Value: 147k; EIA_Code: E96; SizeX_mm: 1.6; SizeY_mm: 0.8; SizeZ_mm: 1; Value2: 0.1W; SizeArea_mm2: 1.28; AEC Qualified: N; VDC_V: 75V; AEC Category: Q200; SizeAreaWB_mm2: 4.68
R89 = CMP-0022711-2: RES, 2.20, 1%, 0.1 W, 0603; Manufacturer: Panasonic; Power_W: 100mW; TempCo: 200 ppm/C; Value_Code: 2R20; U/M: EA; Value: 2.20; Res_ohm: 2.2; SizeX_mm: 1.6; SizeY_mm: 0.8; SizeZ_mm: 1; Value2: 0.1W; SizeArea_mm2: 1.28; CompType: Resistor; AEC Category: Q200
R90 = CMP-0022684-3: RES, 10.0 k, 1%, 0.1 W, 0603; Manufacturer: Panasonic; Power_W: 100mW; TempCo: 100 ppm/C; Value_Code: 10k0; U/M: EA; Value: 10.0k; EIA_Code: E96; Res_ohm: 10k; SizeX_mm: 1.6; SizeY_mm: 0.8; SizeZ_mm: 1; Value2: 0.1W; SizeArea_mm2: 1.28; CompType: Resistor; VDC_V: 75V; AEC Category: Q200
R91 R95 R103 = CMP-0087456-2: 3.3 MOhms ±1% 0.25W, 1/4W Chip Resistor 1206 (3216 Metric) Automotive AEC-Q200, High Voltage Thick Film; Manufacturer: Rohm Semiconductor; AEC Qualified: Yes; Power_W: 250mW; SizeZ_mm: 0.65mm; AEC Grade: Grade 0; TempCo: 100ppm/°C; VDC_V: 500V
R92 = CMP-0026658-1: RES, 10.0 k, 1%, 0.1 W, 0402; Manufacturer: Panasonic; Power_W: 100mW; TempCo: 100 ppm/C; Value_Code: 10k0; U/M: EA; Value: 10.0k; EIA_Code: E96; Res_ohm: 10k; SizeX_mm: 1; SizeY_mm: 0.5; SizeZ_mm: 0.6; Value2: 0.1W; VDC_V: 50V; AEC Category: Q200
R93 R94 = CMP-0025885-5: RES, 0, 5%, 0.1 W, 0603; Manufacturer: Yageo; Power_W: 100mW; TempCo: 200 ppm/C; Value_Code: 0000; Value: 0; EIA_Code: E24; SizeX_mm: 1.6; SizeZ_mm: 1; Value2: 0.1W; SizeArea_mm2: 1.28; AEC Qualified: N; VDC_V: 75V; AEC Category: Q200; SizeY_mm: 0.8; SizeAreaWB_mm2: 4.68
R96 = CMP-0023036-5: RES, 33.2 k, 1%, 0.1 W, 0603; Manufacturer: Yageo; Power_W: 100mW; TempCo: 100 ppm/C; Value_Code: 33k2; Value: 33.2k; EIA_Code: E96; SizeX_mm: 1.6; SizeY_mm: 0.8; SizeZ_mm: 1; Value2: 0.1W; SizeArea_mm2: 1.28; AEC Qualified: N; VDC_V: 75V; AEC Category: Q200; SizeAreaWB_mm2: 4.68
R97 = CMP-0022751-4: RES, 10.0, 1%, 0.1 W, 0603; Manufacturer: Yageo; Power_W: 100mW; TempCo: 100 ppm/C; Value_Code: 10R0; Value: 10.0; EIA_Code: E96; Res_ohm: 10; SizeX_mm: 1.6; SizeY_mm: 0.8; SizeZ_mm: 1; Value2: 0.1W; SizeArea_mm2: 1.28; AEC Qualified: N; VDC_V: 75V; AEC Category: Q200; SizeAreaWB_mm2: 4.68
R98-R100 = CMP-0016708-3: RES, 1.65 k, 1%, 0.25 W, AEC-Q200 Grade 0, 1206; Manufacturer: Vishay-Dale; Power_W: 250mW; TempCo: 100 ppm/C; Value_Code: 1k65; Value: 1.65k; EIA_Code: E96; SizeX_mm: 3.2; SizeY_mm: 1.6; SizeZ_mm: 1.35; Value2: 0.25W; SizeArea_mm2: 5.12; CompType: Resistor; AEC Qualified: Y; VDC_V: 200V; AEC Category: Q200; AEC Grade: 0
R101 R104 = CMP-0024324-2: RES, 536, 0.1%, 0.1 W, 0603; Manufacturer: Yageo America; Power_W: 100mW; TempCo: 25 ppm/C; Value_Code: 536R; U/M: EA; Value: 536; EIA_Code: E192; SizeX_mm: 1.6; SizeY_mm: 0.8; SizeZ_mm: 1; Value2: 0.1W; SizeArea_mm2: 1.28; VDC_V: 75V; AEC Category: Q200
R102 R105 = CMP-0023780-3: RES, 15.0 k, 0.1%, 0.1 W, 0603; Manufacturer: Yageo America; Power_W: 100mW; TempCo: 25 ppm/C; Value_Code: 15k0; U/M: EA; Value: 15.0k; EIA_Code: E192; Res_ohm: 15k; SizeX_mm: 1.6; SizeY_mm: 0.8; SizeZ_mm: 1; Value2: 0.1W; SizeArea_mm2: 1.28; VDC_V: 75V; AEC Category: Q200
R106 = CMP-0022830-5: RES, 16.9 k, 1%, 0.1 W, 0603; Manufacturer: Yageo; Power_W: 100mW; TempCo: 100 ppm/C; Value_Code: 16k9; Value: 16.9k; EIA_Code: E96; SizeX_mm: 1.6; SizeY_mm: 0.8; SizeZ_mm: 1; Value2: 0.1W; SizeArea_mm2: 1.28; AEC Qualified: N; VDC_V: 75V; AEC Category: Q200; SizeAreaWB_mm2: 4.68
R107 = CMP-0023074-4: RES, 39.2, 1%, 0.1 W, 0603; Manufacturer: Yageo; Power_W: 100mW; TempCo: 100 ppm/C; Value_Code: 39R2; Value: 39.2; EIA_Code: E96; SizeX_mm: 1.6; SizeY_mm: 0.8; SizeZ_mm: 1; Value2: 0.1W; SizeArea_mm2: 1.28; AEC Qualified: N; VDC_V: 75V; AEC Category: Q200; SizeAreaWB_mm2: 4.68
R108 R111 = CMP-0023441-3: RES, 15.0 k, 0.1%, 0.1 W, 0603; Manufacturer: Susumu Co Ltd; Power_W: 100mW; TempCo: 25 ppm/C; Value_Code: 15k0; U/M: EA; Value: 15.0k; EIA_Code: E192; Res_ohm: 15k; SizeX_mm: 1.6; SizeY_mm: 0.8; SizeZ_mm: 1; Value2: 0.1W; SizeArea_mm2: 1.28; VDC_V: 75V; AEC Category: Q200
R109 = CMP-0096703-1: NTC Thermistor 470k 0603 (1608 Metric); Manufacturer: TDK; AEC Qualified: No; Res_ohm: 470kΩ; Power_W: 180mW; B 25 50: 4386K; B 25 100: 4480K; SizeZ_mm: 0.9mm; B 25 85: 4455K; B Tolerance: 3%; Tolerance_%: 5%
R110 R112 = CMP-0023630-3: RES, 100 k, 0.1%, 0.1 W, 0603; Manufacturer: Yageo America; Power_W: 100mW; TempCo: 25 ppm/C; U/M: EA; Value: 100k; EIA_Code: E192; SizeX_mm: 1.6; SizeY_mm: 0.8; SizeZ_mm: 1; Value2: 0.1W; SizeArea_mm2: 1.28; VDC_V: 75V; AEC Category: Q200
R? = CMP-0022919-4: RES, 221 k, 1%, 0.1 W, 0603; Manufacturer: Yageo; Power_W: 100mW; TempCo: 100 ppm/C; Value: 221k; EIA_Code: E96; SizeX_mm: 1.6; SizeY_mm: 0.8; SizeZ_mm: 1; Value2: 0.1W; SizeArea_mm2: 1.28; AEC Qualified: N; VDC_V: 75V; AEC Category: Q200; SizeAreaWB_mm2: 4.68
T7 T8 = CMP-0075010-2: Terminal 70A Lug; Manufacturer: Panduit; CNHeader: False; Green_Lifecycle: Not Set; Green_REACh: Incomplete; CompType: Screw Terminal
T9 = CMP-0120309-1: Transformer; Manufacturer: Payton Planar; Ind_H: 250µH; Ns1toNp: 15:2; SizeZ_mm: 10mm; AEC Qualified: No; Frequency_Fixed: 70-160kHz; TaMax_C: +30°C; TaMin_C: -40°C; Voltage_Isolation_Vrms: 2500VDC
TP14 TP19 Vin2 = CMP-0055147-2: Test Point, Multipurpose, Red, TH; Manufacturer: Keystone Electronics; CNHeader: FALSE; Green_Lifecycle: Active; Green_REACh: Passed; ContactFinish: Silver; CT: TRUE
TP15 TP16 = CMP-0055148-2: Test Point, Multipurpose, Black, TH; Manufacturer: Keystone Electronics; CNHeader: FALSE; ContactFinish: Silver; Green_REACh: Passed; Green_Lifecycle: Active; CT: TRUE
TP17 TP18 = CMP-0055148-2: Test Point, Multipurpose, Black, TH; Manufacturer: Keystone Electronics; CNHeader: FALSE; Green_Lifecycle: Active; Green_REACh: Passed; ContactFinish: Silver; CT: TRUE
TP20 = CMP-0055150-2: Test Point, Multipurpose, Orange, TH; Manufacturer: Keystone Electronics; CNHeader: FALSE; Green_Lifecycle: Active; Green_REACh: Passed; ContactFinish: Silver; CT: TRUE
U9 = CMP-0083653-1: Optocoupler, 5.3 kV, 100-200% CTR, SMT; Manufacturer: Vishay-Semiconductor; CTR (Max): 200%; SizeAreaWB_mm2: 71.064; CTR (Min): 100%; SizeZ_mm: 5; SizeX_mm: 8.8; SizeY_mm: 4.58; SizeArea_mm2: 40.304; Voltage_Isolation_Vrms: 5.3kV
U10 = CMP-0079610-1: High Performance Synchronous Rectifier Driver for LLC Resonant Converter, D0008A (SOIC-8); Alternate Manufacturer: Texas Instruments; SizeAreaWB_mm2: 56.58; SizeZ_mm: 1.75; SizeX_mm: 4.9; SizeY_mm: 6.2; SizeArea_mm2: 30.38; CompType: IC; AEC Qualified: N; AEC Category: Q200
U11 = CMP-0095299-1: 750kHz Wide VIN/VOUT Range LLC Controller Optimized for Light Load Efficiency; Manufacturer: Texas Instruments; Number Of Outputs: 2; TaMax_C: +125°C; Output Type: Other; TJmax_C: +150°C; AEC Qualified: No; Standoff Height: 0.1mm; TaMin_C: -40°C; SizeZ_mm: 1.75mm; Switching Frequency: 30-750kHz; Max Supply Voltage: 18.5V
U12 = CMP-0033066-1: Low-Voltage Adjustable Precision Shunt Regulator, 129 ppm / degC, 80 mA, 0 to 70 degC, 3-pin SOT-23 (DBZ), Green (RoHS & no Sb/Br); Manufacturer: Texas Instruments; Min Iz for Regulation(uA): 80; VO Adj(Max)(V): 18; VO Adj(Min)(V): 1.24; Rating: Catalog; SubFamily: Shunt Voltage Reference; Temp Coeff(Max)(ppm/ degree C): 129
